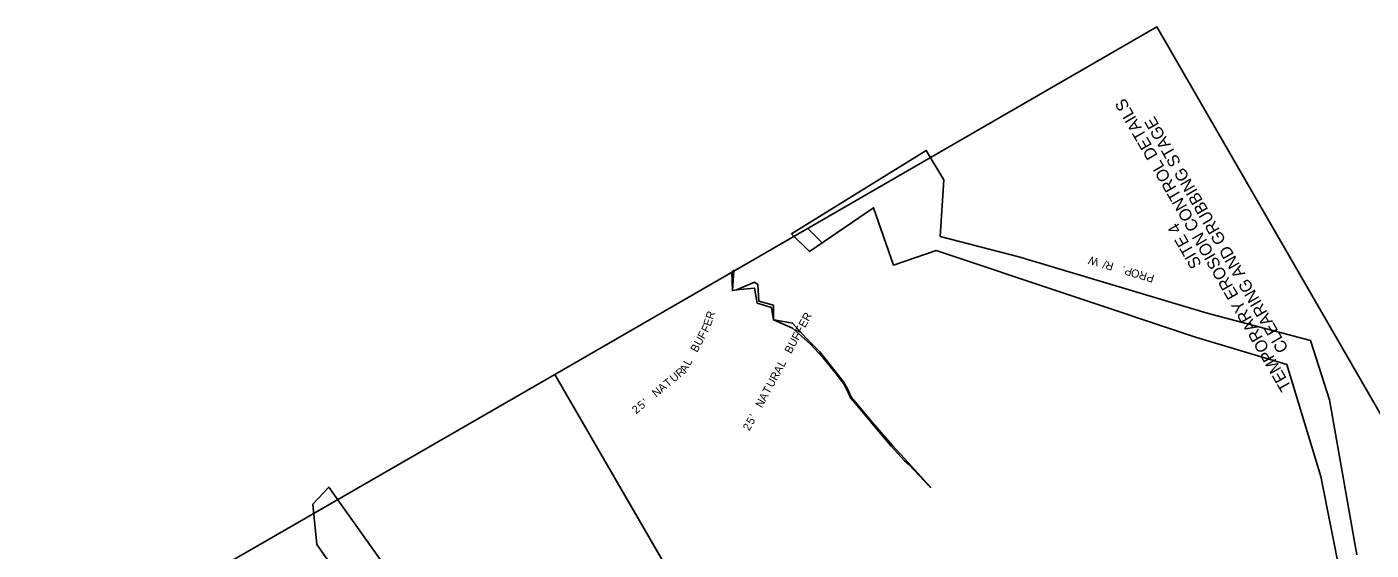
# Model space of a CAD drawing. Extents: x 956270 to 957915, y 1920520 to 1922423.
# Drawn here: x 956270 to 957278, y 1922031 to 1922423 of the extents above; entities that cross this region are included whole.
import ezdxf

# ---------------------------------------------------------------- set-up
doc = ezdxf.new("R2010")
doc.units = 0
for name, color, linetype in [('1', 7, 'Continuous'), ('60', 7, 'Continuous'), ('NO PLOT', 7, 'Continuous'), ('R_Draft', 7, 'Continuous'), ('R_Drainage', 7, 'Continuous'), ('R_Horz Alg', 7, 'Continuous')]:
    doc.layers.add(name, color=color, linetype=linetype)

msp = doc.modelspace()

# ---------------------------------------------------------------- linework, layer by layer
at = {"layer": '1'}
msp.add_line((956816.7, 1921902), (956666.2, 1922162.6), dxfattribs=at)
at = {"layer": 'NO PLOT'}
for points in [[(957915.2, 1921041.6), (957117.5, 1922423.2), (956666.2, 1922162.6), (956816.7, 1921902), (956875.1, 1921935.7), (957087.6, 1921567.7), (957029.2, 1921533.9), (957172.3, 1921286.1), (957225.7, 1921317), (957397.1, 1921020.2), (957343.6, 1920989.3), (957463.8, 1920781)], [(957915.2, 1921041.6), (957117.5, 1922423.2), (956666.2, 1922162.6), (956816.7, 1921902), (956875.1, 1921935.7), (957087.6, 1921567.7), (957029.2, 1921533.9), (957172.3, 1921286.1), (957225.7, 1921317), (957397.1, 1921020.2), (957343.6, 1920989.3), (957463.8, 1920781)], [(957915.2, 1921041.6), (957117.5, 1922423.2), (956666.2, 1922162.6), (956816.7, 1921902), (956875.1, 1921935.7), (957087.6, 1921567.7), (957029.2, 1921533.9), (957172.3, 1921286.1), (957225.7, 1921317), (957397.1, 1921020.2), (957343.6, 1920989.3), (957463.8, 1920781)], [(956931.4, 1922095), (956947.3, 1922078.3), (956947.8, 1922077.9), (956947.8, 1922077.9), (956931.3, 1922096.1), (956918.9, 1922109.4), (956904, 1922126.7), (956891.4, 1922141.7), (956888.2, 1922145.5), (956885.4, 1922151.7), (956882.6, 1922157), (956864.8, 1922179.5), (956854.6, 1922189.7), (956844.3, 1922201), (956830.4, 1922203.4), (956830.1, 1922203.5), (956830.1, 1922203.7), (956830, 1922214.4), (956819.1, 1922217.5), (956818.2, 1922230.1), (956815.9, 1922231.7), (956802.3, 1922226.1), (956802.1, 1922226.1), (956799.4, 1922225.4), (956800.2, 1922240.5), (956798.9, 1922239.4), (956799.4, 1922225.4), (956802.1, 1922226.1), (956815.9, 1922227.3), (956817.7, 1922216), (956828.4, 1922212.8), (956830, 1922203.4), (956844.2, 1922197.2), (956857.7, 1922185.2), (956867.2, 1922175.1), (956877.2, 1922162.8), (956883.1, 1922154.9), (956884.7, 1922151.5), (956885.9, 1922149), (956887.8, 1922145.1), (956891.3, 1922140.9), (956903.8, 1922125.9), (956918.3, 1922108.8), (956928.3, 1922097.8)], [(957012.5, 1920520.4), (956420.5, 1921545.9), (956463.3, 1921570.6), (956365.4, 1921740.1), (956378, 1921747.4), (956270.3, 1921934.1), (956666.2, 1922162.6), (956816.7, 1921902), (956750, 1921863.5), (956962.5, 1921495.4), (957029.2, 1921533.9), (957172.3, 1921286.1), (957120.9, 1921256.4), (957292.2, 1920959.7), (957343.6, 1920989.3), (957463.8, 1920781)], [(957012.5, 1920520.4), (956420.5, 1921545.9), (956463.3, 1921570.6), (956365.4, 1921740.1), (956378, 1921747.4), (956270.3, 1921934.1), (956666.2, 1922162.6), (956816.7, 1921902), (956750, 1921863.5), (956962.5, 1921495.4), (957029.2, 1921533.9), (957172.3, 1921286.1), (957120.9, 1921256.4), (957292.2, 1920959.7), (957343.6, 1920989.3), (957463.8, 1920781)], [(957012.5, 1920520.4), (956420.5, 1921545.9), (956463.3, 1921570.6), (956365.4, 1921740.1), (956378, 1921747.4), (956270.3, 1921934.1), (956666.2, 1922162.6), (956816.7, 1921902), (956750, 1921863.5), (956962.5, 1921495.4), (957029.2, 1921533.9), (957172.3, 1921286.1), (957120.9, 1921256.4), (957292.2, 1920959.7), (957343.6, 1920989.3), (957463.8, 1920781)]]:
    msp.add_lwpolyline(points, close=True, dxfattribs=at)
for points in [[(957267.4, 1922027.1), (957247, 1922143.6), (957232.7, 1922188.1), (957155.2, 1922208.5), (957013.9, 1922250.7), (956955.1, 1922266.1), (956957.7, 1922308.6), (956944.5, 1922330.6), (956843.4, 1922267.9), (956857, 1922254.7), (956905, 1922287.5), (956919.9, 1922244.6), (956952, 1922255.4), (957146.3, 1922190.5), (957215, 1922170), (957240.3, 1922085.9), (957255.1, 1922011.6)], [(956978.4, 1921301), (956892, 1921416.3), (956761.2, 1921624.8), (956685.7, 1921817.7), (956598.6, 1922001.4), (956569.2, 1922006.8), (956549.4, 1922003.6), (956496.6, 1922078), (956484.6, 1922065.1), (956487.7, 1922034.9), (956520.1, 1921988.8), (956538.4, 1921986.1), (956552.8, 1921975.4), (956577.9, 1921905.7), (956667.6, 1921797.4), (956675.5, 1921786), (956734.3, 1921643), (956883.9, 1921386.2), (956963.4, 1921282.8)]]:
    msp.add_lwpolyline(points, dxfattribs=at)
at = {"layer": 'R_Drainage'}
msp.add_lwpolyline([(956857, 1922254.7), (956845.4, 1922266.1)], dxfattribs=at)
at = {"layer": 'R_Horz Alg'}
msp.add_line((956866.5, 1922261.2), (956855.7, 1922272), dxfattribs=at)

# ---------------------------------------------------------------- texts
at = {"layer": '60'}
for s, p in [('TEMPORARY EROSION CONTROL DETAILS', (957218.7, 1922153.1)), ('CLEARING AND GRUBBING STAGE', (957216.4, 1922181.9)), ('SITE 4', (957151.3, 1922245.1))]:
    msp.add_text(s, height=9, rotation=120, dxfattribs=at).set_placement(p)
at = {"layer": 'R_Draft'}
for s, rotation, p in [('W', 163.5297, (957074.5, 1922249.2)), ('/', 163.5297, (957080.1, 1922247.6)), ('R', 163.5297, (957085.5, 1922246)), ('.', 163.5297, (957094.1, 1922243.4)), ('P', 163.5297, (957099.5, 1922241.8)), ('O', 163.5297, (957105.1, 1922240.2)), ('R', 163.5297, (957110.6, 1922238.6)), ('P', 163.5297, (957116, 1922237)), ('E', 71.8782, (956782.9, 1922198.2)), ('R', 71.8782, (956784.6, 1922203.4)), ('E', 61.6353, (956853.7, 1922197.1)), ('R', 61.6353, (956856.3, 1922201.9)), ('F', 61.6353, (956778.1, 1922188.6)), ('F', 61.6353, (956780.7, 1922193.4)), ('F', 61.6353, (956848.6, 1922187.6)), ('F', 61.6353, (956851.1, 1922192.4)), ('B', 61.6353, (956772.7, 1922178.6)), ('U', 61.6353, (956775.4, 1922183.6)), ('B', 61.6353, (956843.2, 1922177.6)), ('U', 61.6353, (956845.8, 1922182.6)), ('U', 39.9648, (956755.4, 1922156.3)), ('R', 39.9648, (956759.8, 1922160)), ('A', 61.6353, (956764.5, 1922163.4)), ('L', 61.6353, (956767.3, 1922168.6)), ('R', 61.6353, (956832.3, 1922157.4)), ('A', 61.6353, (956835, 1922162.4)), ('L', 61.6353, (956837.7, 1922167.6)), ('N', 39.9648, (956742.1, 1922145.1)), ('A', 39.9648, (956746.4, 1922148.8)), ('T', 39.9648, (956750.9, 1922152.5)), ('T', 61.6353, (956826.7, 1922147.2)), ('U', 61.6353, (956829.5, 1922152.3)), ('5', 39.9648, (956731.1, 1922135.9)), ("'", 39.9648, (956735.2, 1922139.4)), ('N', 61.6353, (956821.3, 1922137)), ('A', 61.6353, (956824, 1922142)), ('2', 39.9648, (956727, 1922132.5)), ("'", 61.6353, (956817, 1922129.2)), ('2', 61.6353, (956811.9, 1922119.7)), ('5', 61.6353, (956814.5, 1922124.4))]:
    msp.add_text(s, height=6, rotation=rotation, dxfattribs=at).set_placement(p)

doc.saveas('drawing.dxf')
